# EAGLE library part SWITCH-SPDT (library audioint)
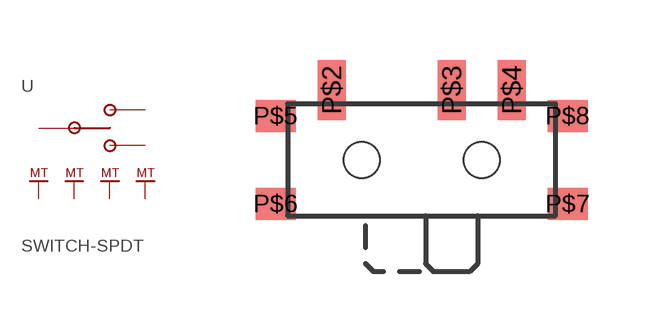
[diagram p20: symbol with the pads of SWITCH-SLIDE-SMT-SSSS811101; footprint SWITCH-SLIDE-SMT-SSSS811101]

Designator prefix -

## SWITCH-SPDTSSSS811101  [SWITCH-SLIDE-SMT-SSSS811101]
P$2  P$2
P$3  P$1
P$4  P$3
P$5  P$4
P$6  P$5
P$7  P$6
P$8  P$7

## Footprint SWITCH-SLIDE-SMT-SSSS811101 (pad centres in mm)
smd 0.7 x 1.5: P$2 -2.25,1.75; P$3 0.75,1.75; P$4 2.25,1.75
smd 1 x 0.8: P$5 -3.65,1.1; P$6 -3.65,-1.1; P$7 3.65,-1.1; P$8 3.65,1.1
hole 0.9 at -1.5,0
hole 0.9 at 1.5,0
